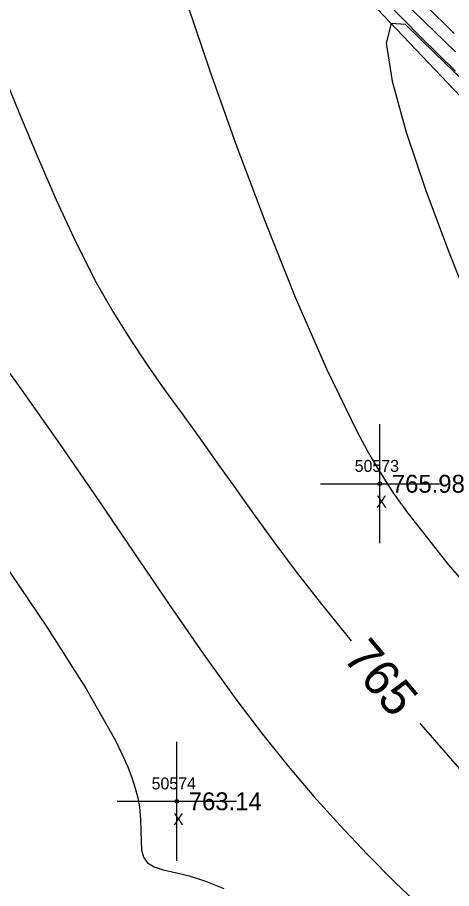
# Model space of a CAD drawing. Extents: x 1378535 to 1380697, y 997729 to 1000024.
# Drawn here: x 1379172.5 to 1379209, y 999280.3 to 999353.4 of the extents above; entities that cross this region are included whole.
import ezdxf

# ---------------------------------------------------------------- set-up
doc = ezdxf.new("R2010")
doc.units = 0
for name, color, linetype in [('RD_DTM_BkLn2', 7, 'Continuous'), ('RD_DTM_Major1', 7, 'Continuous'), ('RD_DTM_Major1_Lbl', 7, 'Continuous'), ('RD_DTM_Minor1', 7, 'Continuous'), ('RD_EX_Misc', 7, 'Continuous'), ('RD_EX_Misc_txCode', 7, 'Continuous'), ('RD_EX_TX_Misc_ELEV', 7, 'Continuous'), ('RD_SMD_Locator', 7, 'Continuous')]:
    doc.layers.add(name, color=color, linetype=linetype)

msp = doc.modelspace()

# ---------------------------------------------------------------- linework, layer by layer
at = {"layer": 'RD_DTM_BkLn2'}
msp.add_lwpolyline([(1379416.856, 999168.193), (1379377.071, 999191.565), (1379325.922, 999232.844), (1379290.492, 999266.41), (1379257.214, 999297.274), (1379219.38, 999336.566), (1379176.35, 999381.85), (1379150.26, 999388.272), (1379142.877, 999355.719), (1379128.704, 999334.594)], dxfattribs=at)
at = {"layer": 'RD_DTM_Major1'}
for points in [[(1379209.286, 999350.493), (1379206.625, 999353.082), (1379203.998, 999355.642)], [(1379171.153, 999349.015), (1379172.61, 999345.439), (1379174.136, 999341.76), (1379175.729, 999338.082), (1379177.387, 999334.51), (1379179.105, 999331.15), (1379180.507, 999328.689), (1379181.938, 999326.39), (1379183.387, 999324.217), (1379184.847, 999322.134), (1379186.309, 999320.104), (1379187.765, 999318.091), (1379189.234, 999316.032), (1379190.735, 999313.916), (1379192.317, 999311.706), (1379194.026, 999309.365), (1379195.911, 999306.856), (1379198.019, 999304.141), (1379200.52, 999301.057)], [(1379206.289, 999294.149), (1379206.381, 999294.04), (1379210.964, 999288.779), (1379215.456, 999283.779), (1379219.585, 999279.343)]]:
    msp.add_lwpolyline(points, dxfattribs=at)
at = {"layer": 'RD_DTM_Minor1'}
for points in [[(1379209.269, 999348.877), (1379206.354, 999351.757), (1379203.436, 999354.719)], [(1379209.184, 999352.056), (1379206.726, 999354.447)], [(1379186.795, 999354.377), (1379188.653, 999348.903), (1379190.84, 999342.763), (1379193.262, 999336.311), (1379195.827, 999329.898), (1379198.441, 999323.875), (1379201.012, 999318.595), (1379201.434, 999317.804), (1379201.856, 999317.038), (1379202.283, 999316.292), (1379202.718, 999315.56), (1379203.165, 999314.836), (1379203.628, 999314.116), (1379203.856, 999313.772), (1379204.088, 999313.428), (1379204.326, 999313.082), (1379204.569, 999312.734), (1379204.818, 999312.383), (1379205.073, 999312.03), (1379208.654, 999307.467), (1379212.867, 999302.605)], [(1379209.975, 999348.028), (1379207.547, 999350.392), (1379205.069, 999352.807), (1379203.866, 999352.893), (1379203.463, 999351.244), (1379203.965, 999348.047), (1379205.15, 999343.762), (1379206.8, 999338.85), (1379208.694, 999333.772), (1379210.611, 999328.987)], [(1379169.426, 999326.776), (1379172.762, 999322.216), (1379176.037, 999317.573), (1379179.197, 999312.968), (1379182.253, 999308.457), (1379185.217, 999304.096), (1379188.1, 999299.938), (1379190.916, 999296.04), (1379193.069, 999293.213), (1379195.215, 999290.542), (1379197.377, 999287.994), (1379199.583, 999285.536), (1379201.858, 999283.133), (1379204.228, 999280.752), (1379207.008, 999278.092)], [(1379171.14, 999307.853), (1379174.992, 999302.178), (1379178.263, 999297.024), (1379180.715, 999292.679), (1379181.265, 999291.555), (1379181.722, 999290.522), (1379182.093, 999289.569), (1379182.381, 999288.686), (1379182.593, 999287.861), (1379182.734, 999287.084), (1379182.831, 999286.042), (1379182.853, 999285.088), (1379182.862, 999284.236), (1379182.916, 999283.499), (1379183.076, 999282.89), (1379183.401, 999282.422), (1379183.957, 999282.086), (1379184.737, 999281.838), (1379185.726, 999281.604), (1379186.91, 999281.31), (1379188.276, 999280.882), (1379189.807, 999280.246)]]:
    msp.add_lwpolyline(points, dxfattribs=at)
at = {"layer": 'RD_EX_Misc'}
for p, q in [((1379202.934, 999309.238), (1379202.934, 999319.238)), ((1379197.934, 999314.238), (1379207.934, 999314.238)), ((1379185.873, 999282.579), (1379185.873, 999292.579)), ((1379180.873, 999287.579), (1379190.873, 999287.579))]:
    msp.add_line(p, q, dxfattribs=at)
at = {"layer": 'RD_SMD_Locator'}
for centre in [(1379202.934, 999314.238), (1379185.873, 999287.579)]:
    msp.add_circle(centre, 0.15, dxfattribs=at)

# ---------------------------------------------------------------- texts
at = {"layer": 'RD_DTM_Major1_Lbl'}
msp.add_text('765', height=3, rotation=309.86551, dxfattribs=at).set_placement((1379199.753, 999299.6))
at = {"layer": 'RD_EX_Misc_txCode'}
for s, p in [('50573', (1379200.816, 999315.238)), ('X', (1379202.619, 999312.238)), ('50574', (1379183.755, 999288.579)), ('X', (1379185.558, 999285.579))]:
    msp.add_text(s, height=1, dxfattribs=at).set_placement(p)
at = {"layer": 'RD_EX_TX_Misc_ELEV'}
for s, p in [('765.98', (1379203.934, 999313.488)), ('763.14', (1379186.873, 999286.829))]:
    msp.add_text(s, height=1.5, dxfattribs=at).set_placement(p)

doc.saveas('drawing.dxf')
